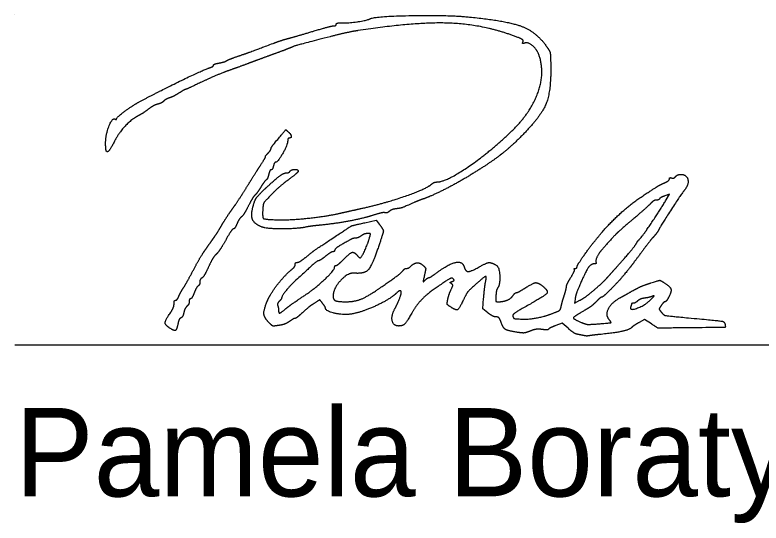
# Model space of a CAD drawing. Extents: x -12 to 164, y -741 to 24.
# Drawn here: x 25.428 to 26.61, y 1.302 to 2.107 of the extents above; entities that cross this region are included whole.
import ezdxf

# ---------------------------------------------------------------- set-up
doc = ezdxf.new("R2010")
doc.units = 0
doc.layers.add('SC_Scratch1', color=7, linetype='Continuous')
doc.layers.add('SH_Data', color=7, linetype='Continuous')

msp = doc.modelspace()

# ---------------------------------------------------------------- linework, layer by layer
at = {"layer": 'SC_Scratch1'}
for points in [[(26.4599, 1.8138), (26.4653, 1.8227), (26.4579, 1.8202)], [(25.9826, 1.7776), (26.0006, 1.7817), (26.0053, 1.7755)], [(26.1775, 1.6348), (26.1692, 1.6412), (26.1707, 1.6582)], [(26.3155, 1.6568), (26.3145, 1.6503), (26.3231, 1.6548)], [(26.4364, 1.6175), (26.4257, 1.6243), (26.4173, 1.6198)], [(26.3045, 1.6105), (26.2953, 1.6188), (26.2848, 1.6147)]]:
    msp.add_lwpolyline(points, dxfattribs=at)
for points in [[(25.99, 2.1002), (25.9968, 2.1044), (26.1138, 2.1067), (26.1482, 2.1033)], [(25.937, 2.0918), (25.937, 2.0931), (25.941, 2.0942), (25.946, 2.094)], [(25.946, 2.094), (25.9556, 2.0937), (25.9866, 2.0981), (25.99, 2.1002)], [(26.2207, 2.0726), (26.1701, 2.0916), (26.0622, 2.0956), (25.9718, 2.0818)], [(26.1482, 2.1033), (26.2075, 2.0975), (26.255, 2.0792), (26.2708, 2.0561)], [(25.8614, 2.0695), (25.8667, 2.0708), (25.8842, 2.0759), (25.9002, 2.0806)], [(25.9002, 2.0806), (25.9163, 2.0854), (25.9312, 2.0893), (25.9332, 2.0893)], [(25.9718, 2.0818), (25.9626, 2.0804), (25.9426, 2.076), (25.9274, 2.0721)], [(25.9332, 2.0893), (25.9353, 2.0893), (25.937, 2.0904), (25.937, 2.0918)], [(25.8374, 2.0616), (25.8453, 2.0646), (25.8561, 2.0681), (25.8614, 2.0695)], [(25.9274, 2.0721), (25.8764, 2.0589), (25.8721, 2.0577), (25.8614, 2.0533)], [(26.233, 2.0639), (26.234, 2.0664), (26.2305, 2.0689), (26.2207, 2.0726)], [(25.781, 2.0411), (25.7957, 2.0461), (25.8022, 2.0485), (25.8374, 2.0616)], [(26.2354, 2.0619), (26.2328, 2.0609), (26.2321, 2.0615), (26.233, 2.0639)], [(26.2588, 2.042), (26.2555, 2.0517), (26.2411, 2.064), (26.2354, 2.0619)], [(25.8614, 2.0533), (25.8588, 2.0522), (25.8485, 2.0484), (25.8386, 2.0448)], [(26.2708, 2.0561), (26.2757, 2.0489), (26.2766, 2.0446), (26.277, 2.0267)], [(25.7516, 2.0304), (25.7565, 2.0314), (25.7617, 2.0329), (25.763, 2.0339)], [(25.763, 2.0339), (25.7643, 2.0349), (25.7724, 2.0381), (25.781, 2.0411)], [(25.8386, 2.0448), (25.8287, 2.0412), (25.8136, 2.0356), (25.805, 2.0324)], [(26.2133, 1.9208), (26.2442, 1.9502), (26.2681, 2.0137), (26.2588, 2.042)], [(25.625, 1.9689), (25.6552, 1.9851), (25.7288, 2.0208), (25.7372, 2.0232)], [(25.7372, 2.0232), (25.7402, 2.0241), (25.7426, 2.0257), (25.7426, 2.0268)], [(25.7426, 2.0268), (25.7426, 2.0279), (25.7466, 2.0295), (25.7516, 2.0304)], [(25.805, 2.0324), (25.7964, 2.0292), (25.7802, 2.0232), (25.769, 2.0193)], [(26.277, 2.0267), (26.2777, 1.9859), (26.2616, 1.9462), (26.2322, 1.9163)], [(25.769, 2.0193), (25.7578, 2.0153), (25.7374, 2.0067), (25.7238, 2.0002)], [(25.7238, 2.0002), (25.7101, 1.9938), (25.6985, 1.9885), (25.6979, 1.9885)], [(25.6979, 1.9885), (25.6974, 1.9885), (25.6929, 1.9859), (25.6879, 1.9828)], [(25.6731, 1.9753), (25.6699, 1.9743), (25.6657, 1.972), (25.6639, 1.9702)], [(25.6879, 1.9828), (25.683, 1.9797), (25.6763, 1.9763), (25.6731, 1.9753)], [(25.589, 1.9423), (25.589, 1.9444), (25.6144, 1.9632), (25.625, 1.9689)], [(25.6542, 1.9653), (25.6507, 1.9645), (25.644, 1.9608), (25.6394, 1.9572)], [(25.6639, 1.9702), (25.6621, 1.9684), (25.6578, 1.9662), (25.6542, 1.9653)], [(25.6394, 1.9572), (25.6348, 1.9537), (25.6276, 1.949), (25.6235, 1.9469)], [(25.5718, 1.9044), (25.5719, 1.9176), (25.5826, 1.9442), (25.5867, 1.9416)], [(25.5867, 1.9416), (25.588, 1.9408), (25.589, 1.9411), (25.589, 1.9423)], [(25.6235, 1.9469), (25.6131, 1.9416), (25.5932, 1.9207), (25.587, 1.9086)], [(25.8392, 1.9033), (25.8577, 1.9255), (25.857, 1.9249), (25.8611, 1.9215)], [(25.8611, 1.9215), (25.8654, 1.9179), (25.8663, 1.9117), (25.8626, 1.9117)], [(26.0966, 1.8421), (26.1107, 1.8421), (26.1788, 1.888), (26.2133, 1.9208)], [(26.2322, 1.9163), (26.2136, 1.8974), (26.1812, 1.8725), (26.1507, 1.8537)], [(25.5732, 1.8907), (25.5724, 1.8915), (25.5718, 1.8977), (25.5718, 1.9044)], [(25.587, 1.9086), (25.5803, 1.8957), (25.575, 1.8888), (25.5732, 1.8907)], [(25.8338, 1.8947), (25.8338, 1.8959), (25.8362, 1.8998), (25.8392, 1.9033)], [(25.8602, 1.9066), (25.8602, 1.901), (25.8443, 1.8733), (25.8411, 1.8733)], [(25.8626, 1.9117), (25.8613, 1.9117), (25.8602, 1.9094), (25.8602, 1.9066)], [(25.829, 1.8877), (25.8316, 1.8903), (25.8338, 1.8935), (25.8338, 1.8947)], [(25.8162, 1.8672), (25.8218, 1.8758), (25.8258, 1.8829), (25.8252, 1.8829)], [(25.8252, 1.8829), (25.8247, 1.8829), (25.8264, 1.885), (25.829, 1.8877)], [(25.8411, 1.8733), (25.84, 1.8733), (25.8384, 1.8706), (25.8376, 1.8673)], [(25.7942, 1.8322), (25.8008, 1.8428), (25.8107, 1.8586), (25.8162, 1.8672)], [(25.8254, 1.8323), (25.8411, 1.8469), (25.8539, 1.8565), (25.8578, 1.8565)], [(25.8339, 1.8613), (25.8327, 1.8613), (25.8311, 1.858), (25.8302, 1.8541)], [(25.8376, 1.8673), (25.8368, 1.864), (25.8351, 1.8613), (25.8339, 1.8613)], [(25.8578, 1.8565), (25.8603, 1.8565), (25.863, 1.8576), (25.8638, 1.8589)], [(25.877, 1.8592), (25.877, 1.8581), (25.8702, 1.8522), (25.862, 1.8461)], [(25.8638, 1.8589), (25.8656, 1.8618), (25.877, 1.8621), (25.877, 1.8592)], [(25.8263, 1.8455), (25.825, 1.8447), (25.8212, 1.8396), (25.8178, 1.8341)], [(25.8302, 1.8541), (25.8293, 1.8502), (25.8276, 1.8463), (25.8263, 1.8455)], [(25.862, 1.8461), (25.8537, 1.84), (25.8412, 1.8292), (25.8342, 1.822)], [(26.1507, 1.8537), (26.1315, 1.8418), (26.0903, 1.8208), (26.0762, 1.8157)], [(26.4572, 1.8407), (26.4615, 1.8427), (26.465, 1.8455), (26.465, 1.847)], [(26.465, 1.847), (26.465, 1.8485), (26.4665, 1.8492), (26.4684, 1.8485)], [(26.4684, 1.8485), (26.4703, 1.8478), (26.4731, 1.8487), (26.4747, 1.8506)], [(26.4747, 1.8506), (26.4763, 1.8525), (26.48, 1.8541), (26.4829, 1.8541)], [(26.4829, 1.8541), (26.4924, 1.8541), (26.4961, 1.838), (26.4887, 1.8291)], [(25.8041, 1.7977), (25.8068, 1.8107), (25.813, 1.8207), (25.8254, 1.8323)], [(25.8178, 1.8341), (25.8144, 1.8286), (25.8103, 1.823), (25.8087, 1.8216)], [(25.9766, 1.8001), (26.0135, 1.8083), (26.0798, 1.8312), (26.0884, 1.8388)], [(26.0884, 1.8388), (26.0905, 1.8406), (26.0942, 1.8421), (26.0966, 1.8421)], [(26.4282, 1.8237), (26.4472, 1.8359), (26.449, 1.837), (26.4572, 1.8407)], [(25.7724, 1.7993), (25.7778, 1.8067), (25.7876, 1.8216), (25.7942, 1.8322)], [(25.8087, 1.8216), (25.807, 1.8203), (25.8023, 1.8127), (25.7983, 1.8047)], [(25.8342, 1.822), (25.8235, 1.8111), (25.8213, 1.8074), (25.8208, 1.7991)], [(26.3336, 1.7312), (26.3559, 1.762), (26.4009, 1.806), (26.4282, 1.8237)], [(26.4887, 1.8291), (26.4845, 1.824), (26.4517, 1.7736), (26.4485, 1.7674)], [(26.0606, 1.8096), (26.0435, 1.8021), (26.0386, 1.8004), (26.032, 1.7997)], [(26.0762, 1.8157), (26.0716, 1.8141), (26.0645, 1.8113), (26.0606, 1.8096)], [(26.4171, 1.7509), (26.4199, 1.7528), (26.4481, 1.7943), (26.4599, 1.8138)], [(26.4439, 1.8133), (26.4417, 1.8133), (26.4377, 1.8108), (26.4351, 1.8079)], [(26.4492, 1.8154), (26.4485, 1.8143), (26.4461, 1.8133), (26.4439, 1.8133)], [(26.4579, 1.8202), (26.4539, 1.8188), (26.45, 1.8166), (26.4492, 1.8154)], [(25.7557, 1.7737), (25.7596, 1.7803), (25.7671, 1.7918), (25.7724, 1.7993)], [(25.7983, 1.8047), (25.7943, 1.7967), (25.7892, 1.7887), (25.787, 1.7869)], [(25.8194, 1.7708), (25.8089, 1.7748), (25.8018, 1.7872), (25.8041, 1.7977)], [(25.8208, 1.7991), (25.8199, 1.7857), (25.824, 1.7828), (25.8446, 1.7823)], [(25.943, 1.7926), (25.9509, 1.7944), (25.966, 1.7978), (25.9766, 1.8001)], [(26.032, 1.7997), (26.0281, 1.7992), (26.0233, 1.7974), (26.0212, 1.7956)], [(26.4351, 1.8079), (26.4324, 1.8049), (26.4199, 1.7938), (26.4074, 1.7833)], [(25.787, 1.7869), (25.7849, 1.7851), (25.7816, 1.7801), (25.7798, 1.7757)], [(25.8446, 1.7823), (25.8638, 1.7817), (25.9217, 1.7878), (25.943, 1.7926)], [(25.9964, 1.7897), (25.9799, 1.7844), (25.9348, 1.7759), (25.911, 1.7736)], [(26.0144, 1.7934), (26.0127, 1.794), (26.0046, 1.7923), (25.9964, 1.7897)], [(26.0212, 1.7956), (26.0191, 1.7938), (26.016, 1.7928), (26.0144, 1.7934)], [(25.7427, 1.753), (25.746, 1.7578), (25.7519, 1.7671), (25.7557, 1.7737)], [(25.7798, 1.7757), (25.7779, 1.7713), (25.7754, 1.7677), (25.7741, 1.7677)], [(25.911, 1.7736), (25.9027, 1.7728), (25.8935, 1.7716), (25.8906, 1.771)], [(25.9286, 1.7512), (25.9602, 1.7722), (25.9616, 1.7729), (25.9826, 1.7776)], [(26.0053, 1.7755), (26.0119, 1.7668), (26.0117, 1.7619), (26.004, 1.7393)], [(26.4074, 1.7833), (26.3878, 1.7668), (26.3761, 1.7554), (26.3594, 1.7365)], [(25.7741, 1.7677), (25.7728, 1.7677), (25.7674, 1.7598), (25.762, 1.7501)], [(25.8906, 1.771), (25.8769, 1.7679), (25.8274, 1.7678), (25.8194, 1.7708)], [(26.4485, 1.7674), (26.4468, 1.764), (26.4429, 1.7585), (26.4399, 1.7553)], [(25.7291, 1.7338), (25.7332, 1.7396), (25.7393, 1.7483), (25.7427, 1.753)], [(25.762, 1.7501), (25.7567, 1.7405), (25.75, 1.7305), (25.7472, 1.7279)], [(25.8894, 1.7233), (25.9031, 1.7344), (25.9011, 1.733), (25.9286, 1.7512)], [(25.9583, 1.7501), (25.9439, 1.7422), (25.9346, 1.7358), (25.9346, 1.7338)], [(25.968, 1.7533), (25.9658, 1.7533), (25.9614, 1.7519), (25.9583, 1.7501)], [(25.9767, 1.7568), (25.9742, 1.7549), (25.9702, 1.7533), (25.968, 1.7533)], [(25.9752, 1.7221), (25.977, 1.7221), (25.9868, 1.7432), (25.9899, 1.7539)], [(25.9866, 1.7604), (25.9837, 1.7604), (25.9793, 1.7587), (25.9767, 1.7568)], [(25.9899, 1.7539), (25.9916, 1.7597), (25.9912, 1.7605), (25.9866, 1.7604)], [(26.4132, 1.7457), (26.4144, 1.7479), (26.4162, 1.7502), (26.4171, 1.7509)], [(26.4399, 1.7553), (26.4369, 1.7521), (26.428, 1.7407), (26.4201, 1.7301)], [(26.004, 1.7393), (25.9937, 1.7094), (25.9818, 1.6964), (25.9658, 1.6977)], [(26.3819, 1.7079), (26.3972, 1.725), (26.4108, 1.7414), (26.4132, 1.7457)], [(25.7102, 1.7017), (25.7165, 1.7136), (25.725, 1.728), (25.7291, 1.7338)], [(25.7472, 1.7279), (25.7443, 1.7254), (25.7388, 1.7163), (25.7349, 1.7077)], [(25.9319, 1.7317), (25.9305, 1.7317), (25.9252, 1.7284), (25.9202, 1.7245)], [(25.9346, 1.7338), (25.9346, 1.7327), (25.9334, 1.7317), (25.9319, 1.7317)], [(25.949, 1.7197), (25.9591, 1.7298), (25.9657, 1.7316), (25.9706, 1.7257)], [(26.3186, 1.7078), (26.3186, 1.7093), (26.3253, 1.7198), (26.3336, 1.7312)], [(26.3594, 1.7365), (26.3535, 1.7299), (26.3473, 1.717), (26.3487, 1.7147)], [(26.4201, 1.7301), (26.4122, 1.7194), (26.4046, 1.7092), (26.4031, 1.7074)], [(25.8722, 1.7115), (25.8722, 1.7133), (25.8737, 1.7149), (25.8756, 1.7149)], [(25.909, 1.7173), (25.9072, 1.7173), (25.8987, 1.71), (25.8734, 1.6868)], [(25.8756, 1.7149), (25.8774, 1.7149), (25.8836, 1.7187), (25.8894, 1.7233)], [(25.9202, 1.7245), (25.9152, 1.7205), (25.9102, 1.7173), (25.909, 1.7173)], [(25.937, 1.7101), (25.9383, 1.7101), (25.9437, 1.7144), (25.949, 1.7197)], [(25.9706, 1.7257), (25.9722, 1.7237), (25.9743, 1.7221), (25.9752, 1.7221)], [(26.0557, 1.7092), (26.0607, 1.7141), (26.0707, 1.7142), (26.0756, 1.7093)], [(26.0938, 1.6966), (26.114, 1.7118), (26.1367, 1.7174), (26.1397, 1.7079)], [(26.1635, 1.7076), (26.1754, 1.7142), (26.1827, 1.7149), (26.1909, 1.7103)], [(26.3487, 1.7147), (26.3495, 1.7135), (26.3484, 1.7125), (26.3465, 1.7125)], [(25.7349, 1.7077), (25.7309, 1.6991), (25.7262, 1.6912), (25.7244, 1.6902)], [(25.8287, 1.6554), (25.8332, 1.6659), (25.8564, 1.6953), (25.8668, 1.7037)], [(25.8668, 1.7037), (25.8697, 1.7061), (25.8722, 1.7096), (25.8722, 1.7115)], [(25.8885, 1.6635), (25.9041, 1.6739), (25.9346, 1.7027), (25.9346, 1.7069)], [(25.9346, 1.7069), (25.9346, 1.7087), (25.9357, 1.7101), (25.937, 1.7101)], [(26.0433, 1.7022), (26.0444, 1.7039), (26.0467, 1.7053), (26.0485, 1.7053)], [(26.0485, 1.7053), (26.0504, 1.7053), (26.0536, 1.707), (26.0557, 1.7092)], [(26.0756, 1.7093), (26.0788, 1.7061), (26.079, 1.7036), (26.0769, 1.6945)], [(26.1397, 1.7079), (26.1421, 1.7004), (26.1502, 1.7002), (26.1635, 1.7076)], [(26.1909, 1.7103), (26.1953, 1.7079), (26.197, 1.6798), (26.1931, 1.6747)], [(26.3088, 1.691), (26.3127, 1.6973), (26.3152, 1.7031), (26.3144, 1.7038)], [(26.3144, 1.7038), (26.3136, 1.7046), (26.3143, 1.7053), (26.3158, 1.7053)], [(26.3158, 1.7053), (26.3173, 1.7053), (26.3186, 1.7064), (26.3186, 1.7078)], [(26.3465, 1.7125), (26.3401, 1.7125), (26.3306, 1.6973), (26.3185, 1.6681)], [(26.3663, 1.6904), (26.3694, 1.694), (26.3764, 1.7018), (26.3819, 1.7079)], [(26.4031, 1.7074), (26.3898, 1.691), (26.3853, 1.6858), (26.3734, 1.6736)], [(25.6948, 1.6741), (25.697, 1.6774), (25.704, 1.6898), (25.7102, 1.7017)], [(25.9658, 1.6977), (25.9554, 1.6986), (25.9322, 1.6732), (25.9322, 1.661)], [(26.0006, 1.6704), (26.0192, 1.6828), (26.0416, 1.6995), (26.0433, 1.7022)], [(26.0769, 1.6945), (26.0746, 1.6842), (26.0747, 1.6837), (26.0785, 1.6872)], [(26.0785, 1.6872), (26.0807, 1.6892), (26.0834, 1.6909), (26.0843, 1.6909)], [(26.0843, 1.6909), (26.0853, 1.6909), (26.0895, 1.6935), (26.0938, 1.6966)], [(26.1736, 1.6831), (26.1755, 1.6925), (26.1728, 1.693), (26.1635, 1.6847)], [(26.3018, 1.6762), (26.3018, 1.678), (26.305, 1.6847), (26.3088, 1.691)], [(26.3462, 1.6716), (26.3541, 1.6784), (26.3632, 1.6869), (26.3663, 1.6904)], [(25.721, 1.6837), (25.721, 1.6812), (25.7199, 1.6785), (25.7185, 1.6776)], [(25.7244, 1.6902), (25.7225, 1.6891), (25.721, 1.6862), (25.721, 1.6837)], [(25.8734, 1.6868), (25.8643, 1.6784), (25.8506, 1.6613), (25.8506, 1.6583)], [(26.1022, 1.6793), (26.0825, 1.6659), (26.0653, 1.6489), (26.057, 1.6345)], [(26.1224, 1.6888), (26.1206, 1.6906), (26.1147, 1.6878), (26.1022, 1.6793)], [(26.1196, 1.6812), (26.1174, 1.6825), (26.1177, 1.6834), (26.1208, 1.6846)], [(26.1189, 1.6713), (26.1218, 1.6776), (26.1219, 1.6797), (26.1196, 1.6812)], [(26.1208, 1.6846), (26.1238, 1.6858), (26.1242, 1.687), (26.1224, 1.6888)], [(26.1635, 1.6847), (26.1476, 1.6707), (26.1439, 1.6663), (26.1384, 1.6549)], [(26.1707, 1.6582), (26.1715, 1.6676), (26.1728, 1.6788), (26.1736, 1.6831)], [(26.2362, 1.6741), (26.2491, 1.6823), (26.2567, 1.6831), (26.2644, 1.6771)], [(26.4062, 1.6696), (26.4141, 1.6741), (26.4273, 1.6798), (26.4355, 1.6823)], [(26.4355, 1.6823), (26.4495, 1.6865), (26.4507, 1.6865), (26.4566, 1.6827)], [(26.4566, 1.6827), (26.4662, 1.6764), (26.4686, 1.669), (26.464, 1.66)], [(25.6879, 1.6615), (25.6895, 1.6651), (25.6926, 1.6708), (25.6948, 1.6741)], [(25.7185, 1.6776), (25.7171, 1.6768), (25.7143, 1.6718), (25.7122, 1.6667)], [(25.9521, 1.6525), (25.9652, 1.6525), (25.9843, 1.6595), (26.0006, 1.6704)], [(26.0296, 1.6405), (26.0337, 1.6482), (26.0402, 1.6644), (26.0402, 1.6672)], [(26.0402, 1.6672), (26.0402, 1.6702), (26.0362, 1.6698), (26.0326, 1.6662)], [(26.1138, 1.6557), (26.1146, 1.6599), (26.1169, 1.6669), (26.1189, 1.6713)], [(26.1931, 1.6747), (26.1918, 1.673), (26.1905, 1.6673), (26.1901, 1.6621)], [(26.217, 1.662), (26.2189, 1.6647), (26.2214, 1.6669), (26.2226, 1.6669)], [(26.2226, 1.6669), (26.2238, 1.6669), (26.2299, 1.6701), (26.2362, 1.6741)], [(26.2644, 1.6771), (26.2741, 1.6694), (26.2672, 1.6615), (26.2357, 1.6438)], [(26.2983, 1.6621), (26.3002, 1.668), (26.3018, 1.6744), (26.3018, 1.6762)], [(26.3185, 1.6681), (26.3174, 1.6654), (26.3161, 1.6604), (26.3155, 1.6568)], [(26.3231, 1.6548), (26.3279, 1.6572), (26.3383, 1.6648), (26.3462, 1.6716)], [(26.3734, 1.6736), (26.3659, 1.666), (26.3589, 1.6597), (26.3578, 1.6597)], [(26.3866, 1.6586), (26.3895, 1.6602), (26.3983, 1.6651), (26.4062, 1.6696)], [(25.6826, 1.6549), (25.684, 1.6549), (25.6864, 1.6578), (25.6879, 1.6615)], [(25.7063, 1.6573), (25.7052, 1.6573), (25.7042, 1.6552), (25.7042, 1.6528)], [(25.7122, 1.6667), (25.7102, 1.6615), (25.7075, 1.6573), (25.7063, 1.6573)], [(25.8304, 1.6197), (25.8228, 1.6273), (25.8222, 1.6401), (25.8287, 1.6554)], [(25.8506, 1.6583), (25.8506, 1.6576), (25.8489, 1.6553), (25.8469, 1.6532)], [(25.857, 1.6412), (25.8645, 1.6473), (25.8698, 1.651), (25.8885, 1.6635)], [(25.9156, 1.6499), (25.9111, 1.6557), (25.9111, 1.6557), (25.9043, 1.6513)], [(25.9322, 1.661), (25.9322, 1.6558), (25.94, 1.6525), (25.9521, 1.6525)], [(26.0326, 1.6662), (26.023, 1.6571), (25.9842, 1.6383), (25.9658, 1.6339)], [(26.1184, 1.6442), (26.1134, 1.6474), (26.1126, 1.6494), (26.1138, 1.6557)], [(26.1901, 1.6621), (26.1896, 1.6545), (26.1903, 1.6525), (26.1935, 1.6525)], [(26.1935, 1.6525), (26.2018, 1.6525), (26.2138, 1.6573), (26.217, 1.662)], [(26.2935, 1.645), (26.2942, 1.6485), (26.2964, 1.6561), (26.2983, 1.6621)], [(26.3578, 1.6597), (26.3567, 1.6597), (26.3528, 1.6565), (26.3492, 1.6527)], [(26.3696, 1.6242), (26.3635, 1.6316), (26.3733, 1.6514), (26.3866, 1.6586)], [(26.4036, 1.6443), (26.4011, 1.6378), (26.4265, 1.6468), (26.435, 1.6554)], [(26.4256, 1.6582), (26.4217, 1.6577), (26.4168, 1.6557), (26.4146, 1.6537)], [(26.4374, 1.6609), (26.4348, 1.6599), (26.4294, 1.6587), (26.4256, 1.6582)], [(26.435, 1.6554), (26.4405, 1.661), (26.4411, 1.6623), (26.4374, 1.6609)], [(26.464, 1.66), (26.4618, 1.6559), (26.4591, 1.6525), (26.458, 1.6525)], [(25.6744, 1.635), (25.6776, 1.6397), (25.6802, 1.6461), (25.6802, 1.6492)], [(25.6802, 1.6492), (25.6802, 1.6523), (25.6813, 1.6549), (25.6826, 1.6549)], [(25.7007, 1.6454), (25.6989, 1.6438), (25.6966, 1.6393), (25.6957, 1.6353)], [(25.7042, 1.6528), (25.7042, 1.6503), (25.7026, 1.647), (25.7007, 1.6454)], [(25.8469, 1.6532), (25.8448, 1.6511), (25.8437, 1.6479), (25.8445, 1.646)], [(25.8445, 1.646), (25.8452, 1.6441), (25.8458, 1.641), (25.8458, 1.6391)], [(25.9043, 1.6513), (25.8961, 1.6459), (25.8935, 1.6439), (25.8823, 1.6339)], [(25.9201, 1.6425), (25.9201, 1.6434), (25.9181, 1.6467), (25.9156, 1.6499)], [(26.1384, 1.6549), (26.1317, 1.6412), (26.1269, 1.6386), (26.1184, 1.6442)], [(26.2357, 1.6438), (26.2224, 1.6364), (26.2162, 1.6315), (26.217, 1.6294)], [(26.2808, 1.6344), (26.2896, 1.6377), (26.2926, 1.6402), (26.2935, 1.645)], [(26.3492, 1.6527), (26.3456, 1.6489), (26.3375, 1.6428), (26.3312, 1.6391)], [(26.405, 1.6491), (26.405, 1.6485), (26.4043, 1.6464), (26.4036, 1.6443)], [(26.4078, 1.6501), (26.4063, 1.6501), (26.405, 1.6496), (26.405, 1.6491)], [(26.4146, 1.6537), (26.4124, 1.6517), (26.4093, 1.6501), (26.4078, 1.6501)], [(26.4521, 1.6467), (26.4486, 1.6413), (26.4487, 1.6404), (26.4525, 1.6357)], [(26.458, 1.6525), (26.4569, 1.6525), (26.4542, 1.6499), (26.4521, 1.6467)], [(25.6727, 1.6113), (25.6657, 1.6161), (25.6662, 1.6229), (25.6744, 1.635)], [(25.6957, 1.6353), (25.6949, 1.6314), (25.6927, 1.6276), (25.691, 1.6269)], [(25.8458, 1.6391), (25.8458, 1.6342), (25.8492, 1.6349), (25.857, 1.6412)], [(25.8823, 1.6339), (25.8775, 1.6296), (25.8727, 1.6261), (25.8716, 1.6261)], [(25.9658, 1.6339), (25.9529, 1.6308), (25.9203, 1.637), (25.9201, 1.6425)], [(26.0363, 1.6141), (26.0279, 1.6141), (26.0239, 1.6299), (26.0296, 1.6405)], [(26.057, 1.6345), (26.0488, 1.6204), (26.0424, 1.6141), (26.0363, 1.6141)], [(26.1905, 1.6285), (26.188, 1.6285), (26.1821, 1.6313), (26.1775, 1.6348)], [(26.231, 1.625), (26.2415, 1.6244), (26.2677, 1.6293), (26.2808, 1.6344)], [(26.3312, 1.6391), (26.3133, 1.6287), (26.3123, 1.6254), (26.3252, 1.6199)], [(26.4525, 1.6357), (26.4561, 1.6312), (26.4611, 1.6302), (26.495, 1.627)], [(25.691, 1.6269), (25.6893, 1.6263), (25.6872, 1.6221), (25.6864, 1.6177)], [(25.8466, 1.6151), (25.8379, 1.6137), (25.8357, 1.6143), (25.8304, 1.6197)], [(25.8631, 1.6213), (25.8595, 1.6187), (25.8521, 1.6159), (25.8466, 1.6151)], [(25.8716, 1.6261), (25.8705, 1.6261), (25.8667, 1.6239), (25.8631, 1.6213)], [(26.1981, 1.6207), (26.1962, 1.6259), (26.1936, 1.6285), (26.1905, 1.6285)], [(26.2234, 1.6042), (26.2084, 1.6066), (26.2016, 1.611), (26.1981, 1.6207)], [(26.217, 1.6294), (26.2184, 1.626), (26.2191, 1.6257), (26.231, 1.625)], [(26.3252, 1.6199), (26.332, 1.617), (26.3385, 1.6164), (26.352, 1.6175)], [(26.352, 1.6175), (26.3715, 1.619), (26.3733, 1.6197), (26.3696, 1.6242)], [(26.4173, 1.6198), (26.4127, 1.6173), (26.4074, 1.6138), (26.4056, 1.612)], [(26.495, 1.627), (26.5441, 1.6225), (26.5524, 1.621), (26.5533, 1.6162)], [(25.6864, 1.6177), (25.6845, 1.608), (25.6803, 1.606), (25.6727, 1.6113)], [(26.2634, 1.6086), (26.2576, 1.6094), (26.2503, 1.6084), (26.2445, 1.6061)], [(26.2735, 1.609), (26.2731, 1.6081), (26.2685, 1.6079), (26.2634, 1.6086)], [(26.2848, 1.6147), (26.2789, 1.6124), (26.2739, 1.6099), (26.2735, 1.609)], [(26.3191, 1.601), (26.3161, 1.6017), (26.3095, 1.6059), (26.3045, 1.6105)], [(26.4056, 1.612), (26.4019, 1.6082), (26.3804, 1.6034), (26.357, 1.6009)], [(26.483, 1.6111), (26.4473, 1.6107), (26.4469, 1.6107), (26.4364, 1.6175)], [(26.5533, 1.6162), (26.5541, 1.612), (26.5521, 1.6118), (26.483, 1.6111)], [(26.2445, 1.6061), (26.2375, 1.6033), (26.232, 1.6028), (26.2234, 1.6042)], [(26.3294, 1.5989), (26.3268, 1.5994), (26.3221, 1.6004), (26.3191, 1.601)], [(26.3378, 1.5986), (26.3358, 1.5982), (26.332, 1.5983), (26.3294, 1.5989)], [(26.357, 1.6009), (26.3484, 1.6001), (26.3398, 1.599), (26.3378, 1.5986)]]:
    msp.add_open_spline(points, degree=2, dxfattribs=at)
at = {"layer": 'SH_Data'}
for p, q in [((25.4281, 2.1066), (25.4281, 2.1066)), ((25.4281, 1.5843), (28.9281, 1.5843))]:
    msp.add_line(p, q, dxfattribs=at)

# ---------------------------------------------------------------- texts
at = {"layer": 'SC_Scratch1'}
msp.add_text('Pamela Boratyn', height=0.14, dxfattribs=at).set_placement((25.4281, 1.3443))

doc.saveas('drawing.dxf')
